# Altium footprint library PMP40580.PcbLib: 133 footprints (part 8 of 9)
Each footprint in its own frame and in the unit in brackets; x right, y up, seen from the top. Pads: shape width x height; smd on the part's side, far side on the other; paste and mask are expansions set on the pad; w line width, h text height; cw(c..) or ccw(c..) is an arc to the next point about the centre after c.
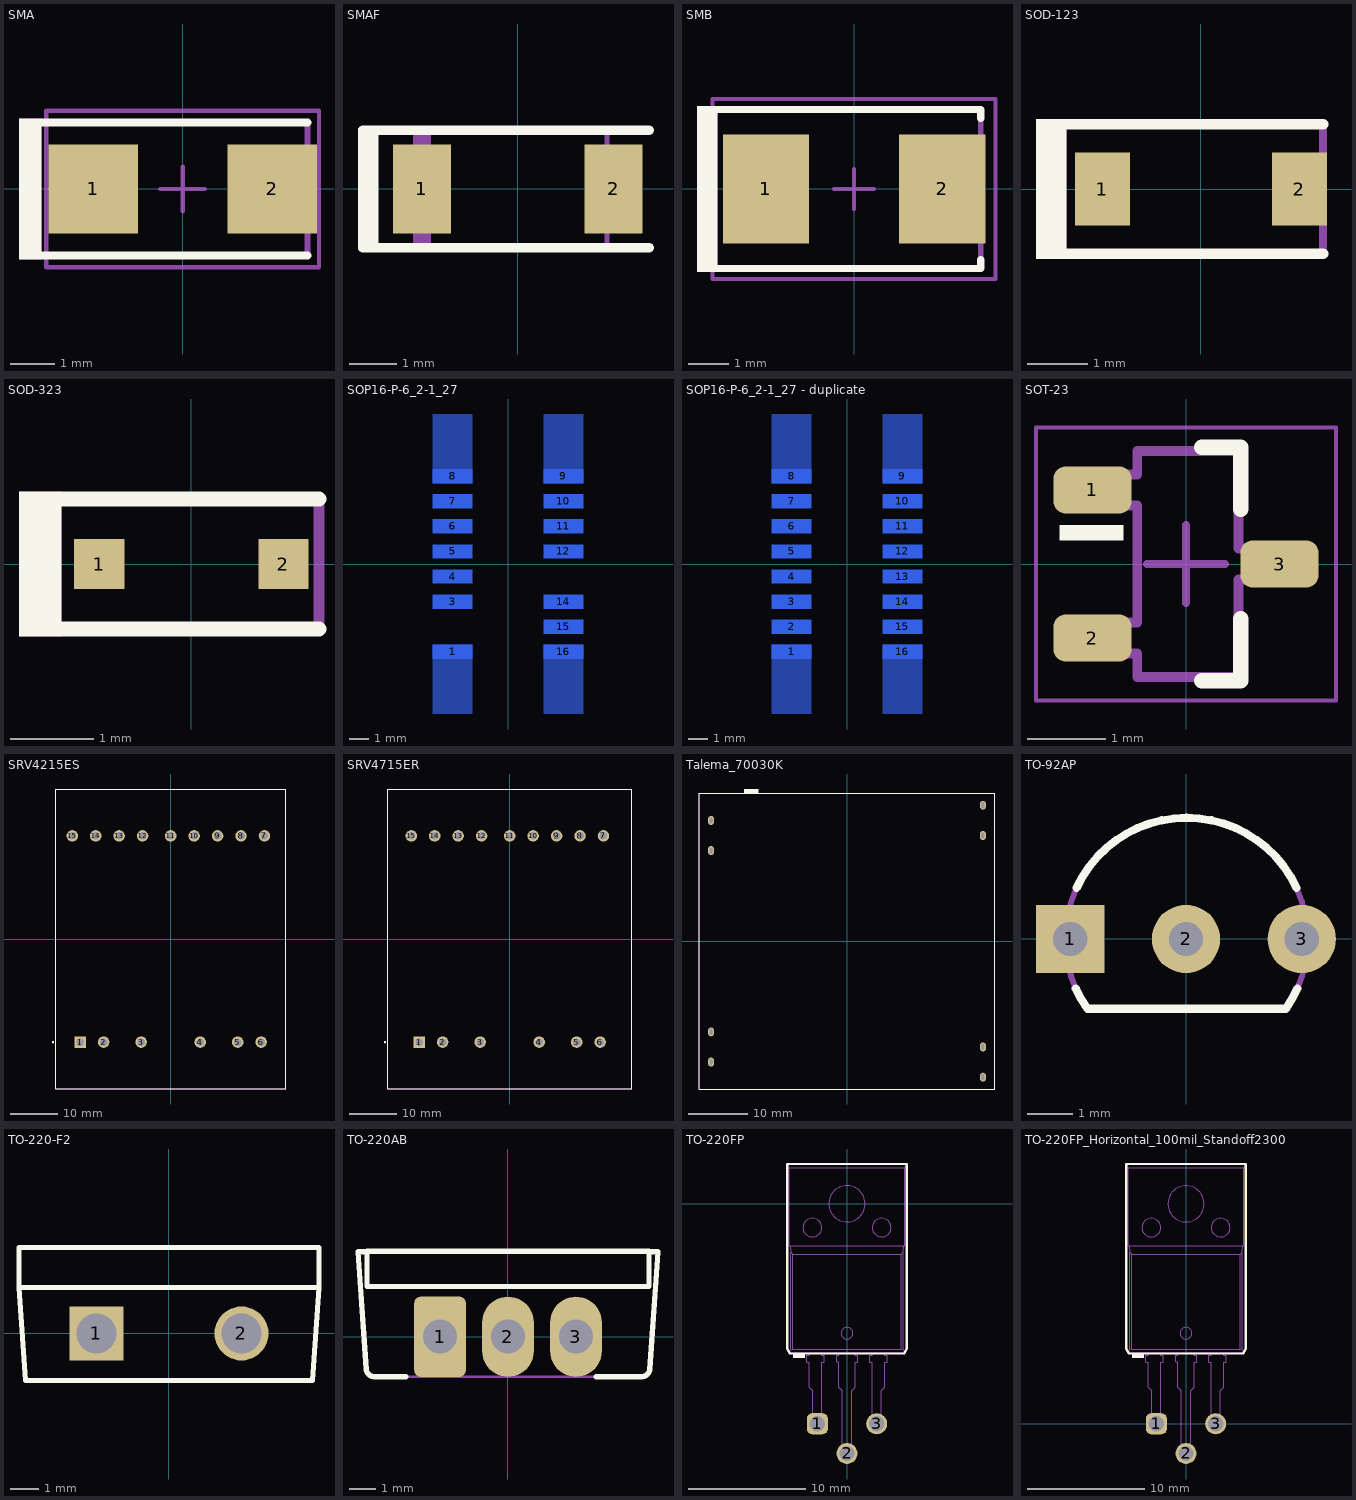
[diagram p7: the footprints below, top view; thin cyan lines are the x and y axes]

## SMA [mm] "Molded Diode, 2-Leads, Body 4.3x2.6mm, IPC Medium Density, based on OnSemi component dimensions and land pattern"
height 2.27
pads (2):
  rect 2x2 smd: 1(-2,0) 2(2,0)
Top Overlay:
  rectangle: -3.658,-1.575 -3.15,1.575
  lines w0.178: -3.327,-1.486 2.794,-1.486 ; -3.327,1.486 2.794,1.486
Mechanical 5:
  rectangle: -3.658,-1.575 -3.15,1.575
  lines w0.127: -3.327,-1.486 2.794,-1.486 2.794,1.486 -3.327,1.486
  text ".Designator" at -2.769,-0.33 h1.02
Mechanical 15:
  lines w0.1: -0.5,0 0.5,0 ; 0,-0.5 0,0.5 ; -3.05,-1.75 -3.05,1.75 3.05,1.75 3.05,-1.75 -3.05,-1.75
3D body "SMA_nominal.stp": height 2.42, standoff 0.02, extent -2.6,-1.3 2.6,1.3

## SMAF [mm] "SMD, 2-Leads, Body 3.8x2.5mm"
height 1
pads (2):
  rect 1.24x1.89 smd: 1(-2.04,0) 2(2.04,0)
Top Overlay:
  rectangle: -3.4,-1.3 -2.96,1.3
  lines w0.2: -3.3,-1.25 2.8,-1.25 ; -3.3,1.25 2.8,1.25
Mechanical 5:
  rectangle: -2.23,-1.3 -1.9,1.3
  lines w0.1: -1.9,-0.875 -1.9,-1.25 1.9,-1.25 1.9,-0.875 ; -1.9,0.875 -1.9,1.25 1.9,1.25 1.9,0.875 ; -1.878,-0.875 -1.878,0.875 ; 1.878,-0.875 1.878,0.875
  text ".Designator" at -1.499,-0.33 h0.9
3D body "SMAF.stp": height 1, standoff 0, extent -2.35,-1.25 2.35,1.25

## SMB [mm] "Molded Diode, 2-Leads, Body 5.4x3.6mm, IPC Medium Density, based on OnSemi component dimensions"
height 2.65
pads (2):
  rect 2.159x2.743 smd: 1(-2.21,0) 2(2.21,0)
Top Overlay:
  rectangle: -3.937,-2.083 -3.429,2.083
  lines w0.178: -3.607,-1.994 3.175,-1.994 3.175,-1.765 ; -3.607,1.994 3.175,1.994 3.175,1.765
Mechanical 5:
  rectangle: -3.937,-2.083 -3.429,2.083
  lines w0.127: -3.607,-1.994 3.175,-1.994 3.175,-1.765 3.175,1.765 3.175,1.994 -3.607,1.994
  text ".Designator" at -2.311,-0.508 h1.02
Mechanical 15:
  lines w0.1: -0.5,0 0.5,0 ; 0,-0.5 0,0.5 ; -3.55,-2.25 -3.55,2.25 3.55,2.25 3.55,-2.25 -3.55,-2.25
3D body "SMB_nominal.stp": height 2.32, standoff 0.02, extent -2.7,-1.8 2.7,1.8

## SOD-123 [mm] "On Semi recommended land pattern"
height 1.35
pads (2):
  rect 0.915x1.22 smd: 1(-1.637,0) 2(1.637,0)
Top Overlay:
  rectangle: -2.743,-1.168 -2.235,1.168
  lines w0.178: -2.413,-1.079 2.032,-1.079 ; -2.413,1.079 2.032,1.079
Mechanical 5:
  rectangle: -2.743,-1.168 -2.235,1.168
  lines w0.127: -2.413,-1.079 2.032,-1.079 2.032,1.079 -2.413,1.079
  text ".Designator" at -1.956,-0.33 h0.76
3D body "SOD-123.stp": height 1.35, standoff 0, extent -1.932,-0.9 1.932,0.9

## SOD-323 [mm] "NXP recommended land pattern"
height 1.15
pads (2):
  rect 0.6x0.6 smd paste-0.05: 1(-1.1,0) 2(1.1,0)
Top Overlay:
  rectangle: -2.057,-0.864 -1.549,0.864
  lines w0.178: -1.803,-0.775 0.1,-0.775 1.525,-0.775 ; -1.803,0.775 0.1,0.775 1.525,0.775
Mechanical 5:
  rectangle: -2.057,-0.864 -1.549,0.864
  lines w0.127: -1.803,-0.775 0.1,-0.775 1.525,-0.775 1.525,0.775 0.1,0.775 -1.803,0.775
  text ".Designator" at -1.4,-0.275 h0.76
3D body "SOD-323.stp": height 1.1, standoff 0, extent -1.3,-0.675 1.3,0.675

## SOP16-P-6_2-1_27 [mm]
pads (14):
  rect 2x0.7 smd far side: 1(-2.8,-4.445) 3(-2.8,-1.905) 4(-2.8,-0.635) 5(-2.8,0.635) 6(-2.8,1.905) 7(-2.8,3.175) 8(-2.8,4.445) 9(2.8,4.445) 10(2.8,3.175) 11(2.8,1.905) 12(2.8,0.635) 14(2.8,-1.905) 15(2.8,-3.175) 16(2.8,-4.445)
Bottom Layer:
  region: -3.8,-7.592 -3.8,-4.092 -1.8,-4.092 -1.8,-7.592
  region: 1.8,-7.592 1.8,-4.092 3.8,-4.092 3.8,-7.592
  region: 1.8,4.093 1.8,7.593 3.8,7.593 3.8,4.093
  region: -3.8,4.093 -3.8,7.593 -1.8,7.593 -1.8,4.093
Bottom Overlay:
  circle w0.5: c-1.05,-5.945 r0.25
  circle w0.15: c-0.9,-4.445 r0.224
  lines w0.15: -1.3,-5.145 -1.3,5.145 1.3,5.145 1.3,-5.145 0.4,-5.145 0.4,-4.502 -0.4,-4.502 -0.4,-5.145 -1.3,-5.145
  lines w0.5: -3.8,-3.81 -1.8,-3.81 ; -3.8,-2.54 -1.8,-2.54 ; -3.8,-1.27 -1.8,-1.27 ; -3.8,0 -1.8,0 ; -3.8,1.27 -1.8,1.27 ; -3.8,2.54 -1.8,2.54 ; -3.8,3.81 -1.8,3.81 ; 1.8,-3.81 3.8,-3.81 ; 1.8,-2.54 3.8,-2.54 ; 1.8,-1.27 3.8,-1.27 ; 1.8,0 3.8,0 ; 1.8,1.27 3.8,1.27 ; 1.8,2.54 3.8,2.54 ; 1.8,3.81 3.8,3.81

## SOP16-P-6_2-1_27 - duplicate [mm]
pads (16):
  rect 2x0.7 smd far side: 1(-2.8,-4.445) 2(-2.8,-3.175) 3(-2.8,-1.905) 4(-2.8,-0.635) 5(-2.8,0.635) 6(-2.8,1.905) 7(-2.8,3.175) 8(-2.8,4.445) 9(2.8,4.445) 10(2.8,3.175) 11(2.8,1.905) 12(2.8,0.635) 13(2.8,-0.635) 14(2.8,-1.905) 15(2.8,-3.175) 16(2.8,-4.445)
Bottom Layer:
  region: -3.8,-7.592 -3.8,-4.092 -1.8,-4.092 -1.8,-7.592
  region: 1.8,-7.592 1.8,-4.092 3.8,-4.092 3.8,-7.592
  region: 1.8,4.093 1.8,7.593 3.8,7.593 3.8,4.093
  region: -3.8,4.093 -3.8,7.593 -1.8,7.593 -1.8,4.093
Bottom Overlay:
  circle w0.5: c-1.05,-5.945 r0.25
  circle w0.15: c-0.9,-4.445 r0.224
  lines w0.15: -1.3,-5.145 -1.3,5.145 1.3,5.145 1.3,-5.145 0.4,-5.145 0.4,-4.502 -0.4,-4.502 -0.4,-5.145 -1.3,-5.145
  lines w0.5: -3.8,-3.81 -1.8,-3.81 ; -3.8,-2.54 -1.8,-2.54 ; -3.8,-1.27 -1.8,-1.27 ; -3.8,0 -1.8,0 ; -3.8,1.27 -1.8,1.27 ; -3.8,2.54 -1.8,2.54 ; -3.8,3.81 -1.8,3.81 ; 1.8,-3.81 3.8,-3.81 ; 1.8,-2.54 3.8,-2.54 ; 1.8,-1.27 3.8,-1.27 ; 1.8,0 3.8,0 ; 1.8,1.27 3.8,1.27 ; 1.8,2.54 3.8,2.54 ; 1.8,3.81 3.8,3.81

## SOT-23 [mm] "SOT23, 3-Leads, Body 2.9x1.3mm, Pitch 0.95mm, Lead Span 2.5mm, IPC Medium Density"
height 1.1
pads (3):
  rrect50% 1x0.6 smd: 1(-1.2,0.95) 2(-1.2,-0.95) 3(1.2,0)
Top Overlay:
  rectangle: -1.625,0.3 -0.8,0.5
  lines w0.2: 0.2,-1.5 0.7,-1.5 0.7,-0.7 ; 0.2,1.5 0.7,1.5 0.7,0.7
Mechanical 5:
  lines w0.127: -1.16,-1.15 -1.16,-0.75 -0.625,-0.75 -0.625,0.75 -1.16,0.75 -1.16,1.15 -0.625,1.15 -0.625,1.45 0.675,1.45 0.675,0.2 1.21,0.2 1.21,-0.2 0.675,-0.2 0.675,-1.45 -0.625,-1.45 -0.625,-1.15 -1.16,-1.15
  text ".Designator" at -0.175,1.225 h0.64
Mechanical 15:
  lines w0.05: -1.925,-1.75 1.925,-1.75 1.925,1.75 -1.925,1.75 -1.925,-1.75
  lines w0.1: -0.5,0 0.5,0 ; 0,-0.5 0,0.5
3D body "SW3dPS-sot-3p290x130ll237h100.STEP": height 1, standoff 0, extent -1.16,-1.45 1.21,1.45

## SRV4215ES [mm]
pads (15):
  rrect4% 2.45x2.45 hole 1.6 paste-1000 mask+0: 1(-19.3,-22)
  round 2.45 hole 1.6 paste-1000 mask+0: 2(-14.3,-22) 3(-6.3,-22) 4(6.3,-22) 5(14.3,-22) 6(19.3,-22) 7(20,22) 8(15,22) 9(10,22) 10(5,22) 11(0,22) 12(-6,22) 13(-11,22) 14(-16,22) 15(-21,22)
Top Overlay:
  circle w0.25: c-25.1,-22 r0.125
  lines w0.2: -24.5,-32 -24.5,32 24.5,32 24.5,-32 -24.5,-32
Mechanical 5:
  lines w0.1: -24.5,-32 -24.5,32 24.5,32 24.5,-32 -24.5,-32
  text ".Designator" at 0,0 h0.5
3D body "Trans_SRV4215ES_SMT_TRANSFORMER.STEP": height 0.25, standoff 0, extent -24.6,-32.1 24.6,32.1

## SRV4715ER [mm]
pads (15):
  rrect4% 2.45x2.45 hole 1.6 paste-1000 mask+0: 1(-19.3,-22)
  round 2.45 hole 1.6 paste-1000 mask+0: 2(-14.3,-22) 3(-6.3,-22) 4(6.3,-22) 5(14.3,-22) 6(19.3,-22) 7(20,22) 8(15,22) 9(10,22) 10(5,22) 11(0,22) 12(-6,22) 13(-11,22) 14(-16,22) 15(-21,22)
Top Overlay:
  circle w0.25: c-26.6,-22 r0.125
  lines w0.2: -26,-32 26,-32 26,32 -26,32 -26,-32
Mechanical 5:
  lines w0.1: -26,-32 26,-32 26,32 -26,32 -26,-32
  text ".Designator" at 0,0 h0.5
3D body "Trans_SRV4715ER_PTH_TRANSFORMER_64MM0_52MM0.STEP": height 0.25, standoff 0, extent -26.1,-32.1 26.1,32.1

## Talema_70030K [mm] "TH, 8-Leads, Body 49.7x49.7mm"
height 23.1
pads (8):
  oval 1x1.5 hole 0.5 slot 1 at 90 deg: 3(-22.86,20.32) 4(-22.86,15.24) 5(-22.86,-15.24) 6(-22.86,-20.32) 11(22.86,-22.86) 12(22.86,-17.78) 13(22.86,17.78) 14(22.86,22.86)
Top Overlay:
  rectangle: -17.3,24.85 -14.9,25.6
  lines w0.2: -24.85,-24.85 -24.85,24.85 24.85,24.85 24.85,-24.85 -24.85,-24.85
Mechanical 5:
  lines w0.1: -24.85,-24.85 24.85,-24.85 24.85,24.85 -24.85,24.85 -24.85,-24.85

## TO-92AP [mm] "TO, Flat Index; 3 In-Line, Axial Leads; Body Dia. 5mm; Leads 0.55 x 0.50 mm (max)"
height 5.2
pads (3):
  rect 1.5x1.5 hole 0.75: 1(-2.54,0)
  round 1.5 hole 0.75: 2(0,0) 3(2.54,0)
Top Overlay:
  lines w0.178: -2.417,-1.082 ccw(c0.013,0) -2.163,-1.53 2.189,-1.53 ccw(c0.013,0) 2.443,-1.082 ; -2.398,1.124 cw(c0.013,0) 2.424,1.124
Mechanical 5:
  lines w0.127: -2.635,-0.25 -2.875,-0.25 -2.875,0.25 -2.635,0.25 ; 2.661,-0.25 2.865,-0.25 2.865,0.25 2.661,0.25 ; -2.647,0 cw(c0.013,0) 2.673,0 cw(c0.013,0) 2.189,-1.53 -2.163,-1.53 cw(c0.013,0) -2.647,0
  text ".Designator" at -1.9,-0.5 h1.02
3D body "TO-92AP.stp": height 9.33, standoff -8.7, extent -2.87,-1.53 2.87,2.66

## TO-220-F2 [mm] "CREE"
height 20.066
pads (2):
  rect 1.9x1.9 hole 1.4: 1(-2.54,0)
  round 1.9 hole 1.4: 2(2.54,0)
Top Overlay:
  lines w0.178: -5.255,1.608 -5.255,3.008 5.255,3.008 5.255,1.608 ; -5.255,1.608 5.255,1.608 ; -5.255,1.608 -5.028,-1.642 5.028,-1.642 5.255,1.608
Mechanical 5:
  lines w0.127: -5.255,1.608 -5.028,-1.642 5.028,-1.642 5.255,1.608 ; -5.255,1.608 5.255,1.608 ; -5.255,1.608 -5.255,3.008 5.255,3.008 5.255,1.608
  text ".Designator" at -4.064,-0.308 h1.02
3D body "TO-220AC.stp": height 19.09, standoff -3.99, extent -5.255,-1.645 5.255,3.008

## TO-220AB [mm] "Copied from Altium's version of TO3B"
height 19.4
pads (3):
  rrect25% 1.93x3 hole 1.27: 1(-2.54,0)
  oval 1.93x3 hole 1.27: 2(0,0) 3(2.54,0)
Top Overlay:
  lines w0.2: -5.27,3.175 -5.606,3.175 ; -5.27,3.185 -5.606,3.185 -5.606,3.175 ; -3.81,-1.495 -5,-1.495 cw(c-5,-1.195) -5.297,-1.237 cw(c-5,-1.195) -5.299,-1.216 -5.606,3.175 ; 3.302,-1.495 5,-1.495 ccw(c5,-1.195) 5.297,-1.237 ccw(c5,-1.195) 5.3,-1.216 5.607,3.175 ; 5.27,3.175 5.607,3.175 ; 5.27,3.185 5.607,3.185 5.607,3.175 ; -5.27,1.875 -5.27,3.195 5.27,3.195 5.27,1.875 -5.27,1.875
Mechanical 5:
  lines w0.1: -5.27,3.175 -5.606,3.175 ; -5.27,3.185 -5.606,3.185 -5.606,3.175 ; 5.27,3.175 5.607,3.175 ; 5.27,3.185 5.607,3.185 5.607,3.175 ; -5.606,3.175 -5.299,-1.216 ccw(c-5,-1.195) -5.297,-1.237 ccw(c-5,-1.195) -5,-1.495 5,-1.495 ccw(c5,-1.195) 5.297,-1.237 ccw(c5,-1.195) 5.3,-1.216 5.607,3.175 ; -5.27,1.875 5.27,1.875 5.27,3.195 -5.27,3.195 -5.27,1.875
  text ".Designator" at -1.524,-0.508 h1.02
3D body "TO-220AB.stp": height 19.42, standoff -3.88, extent -5.606,-1.495 5.607,3.195

## TO-220FP [mm] "TH, 3-Leads, Body 10.4x16mm"
height 6.9
pads (3):
  rrect50% 1.8x1.8 hole 1.3: 1(-2.54,-18.796)
  round 1.8 hole 1.3: 2(0,-21.336) 3(2.54,-18.796)
Top Overlay:
  rectangle: -4.6,-13.196 -3.6,-12.796
  lines w0.2: -5.1,-12.396 -5.1,3.404 5.1,3.404 5.1,-12.396 4.9,-12.796 3.5,-12.796 -4.9,-12.796 -5.1,-12.396
Mechanical 5:
  circle w0.1: c0,0.009 r1.55
  lines w0.1: -5.09,3.391 -5.09,-12.458 -4.917,-12.741 -4.883,-12.741 ; -5.09,3.391 -4.927,3.109 ; -5.09,3.391 -4.95,3.409 4.95,3.409 5.09,3.391 ; -4.927,3.109 -4.927,-3.591 -4.847,-3.591 ; -4.927,3.109 4.927,3.109 ; -4.883,-12.741 -4.81,-12.477 ; -4.883,-12.741 4.883,-12.741 ; -4.847,-3.591 4.847,-3.591 ; -4.847,-3.591 -4.81,-4.149 ; -4.81,-12.477 -4.65,-12.441 ; -4.81,-12.477 -4.81,-4.149 ; -4.81,-4.149 -4.65,-4.298 ; -4.65,-12.441 -4.65,-4.298 ; -4.65,-12.441 4.65,-12.441 ; -4.65,-4.298 4.65,-4.298 ; -2.94,-18.041 -2.14,-18.041 ; -2.94,-18.041 -2.94,-15.991 -3.24,-15.691 -3.24,-13.541 -3.44,-13.541 -3.44,-12.941 -3.24,-12.941 -3.24,-12.741 -2.14,-12.741 -2.14,-12.941 -1.94,-12.941 -1.94,-13.541 -2.14,-13.541 -2.14,-18.041 ; -2.94,-18.041 -2.94,-19.041 -2.14,-19.041 -2.14,-18.041 ; -0.4,-20.581 0.4,-20.581 ; -0.4,-20.581 -0.4,-15.991 -0.7,-15.691 -0.7,-13.509 -0.897,-13.509 -0.897,-12.941 -0.7,-12.941 -0.7,-12.741 0.7,-12.741 0.7,-12.941 0.9,-12.941 0.9,-13.541 0.7,-13.541 0.7,-15.691 0.4,-15.991 0.4,-20.581 ; -0.4,-20.581 -0.4,-21.581 0.4,-21.581 0.4,-20.581 ; 2.14,-18.041 2.94,-18.041 ; 2.14,-18.041 2.14,-13.541 1.94,-13.541 1.94,-12.941 2.14,-12.941 2.14,-12.741 3.24,-12.741 3.24,-12.941 3.44,-12.941 3.44,-13.541 3.24,-13.541 3.24,-15.691 2.94,-15.991 2.94,-18.041 ; 2.14,-18.041 2.14,-19.041 2.94,-19.041 2.94,-18.041 ; 4.65,-12.441 4.65,-4.298 ; 4.65,-12.441 4.81,-12.477 ; 4.65,-4.298 4.81,-4.149 ; 4.81,-12.477 4.81,-4.149 ; 4.81,-12.477 4.883,-12.741 ; 4.81,-4.149 4.847,-3.591 ; 4.847,-3.591 4.927,-3.591 4.927,3.109 ; 4.883,-12.741 4.917,-12.741 5.09,-12.458 5.09,3.391 ; 4.927,3.109 5.09,3.391 ; -3.768,-2.029 ccw(c-2.968,-2.029) -2.168,-2.029 ccw(c-2.968,-2.029) -3.768,-2.029 ; -0.5,-11.055 cw(c0,-11.055) 0.5,-11.055 cw(c0,-11.055) -0.5,-11.055 ; 2.168,-2.029 ccw(c2.968,-2.029) 3.768,-2.029 ccw(c2.968,-2.029) 2.168,-2.029
  text ".Designator" at -3.1,-9.996 h1.85
3D body "TO-220FP_Horizontal_100mil_Standoff2300.stp": height 7.02, standoff -1.57, extent -5.09,-21.581 5.09,3.409

## TO-220FP_Horizontal_100mil_Standoff2300 [mm] "TH, 3-Leads, Body 10.4x16mm"
height 6.9
pads (3):
  rrect50% 1.8x1.8 hole 1.3: 1(-2.54,0)
  round 1.8 hole 1.3: 2(0,-2.54) 3(2.54,0)
Top Overlay:
  rectangle: -4.6,5.6 -3.6,6
  lines w0.2: -5.1,6.4 -5.1,22.2 5.1,22.2 5.1,6.4 4.9,6 3.5,6 -4.9,6 -5.1,6.4
Mechanical 5:
  lines w0.1: -5.09,22.187 -5.09,6.338 -4.917,6.055 -4.883,6.055 ; -5.09,22.187 -4.927,21.905 ; -5.09,22.187 -4.95,22.205 4.95,22.205 5.09,22.187 ; -4.927,21.905 -4.927,15.205 -4.847,15.205 ; -4.927,21.905 4.927,21.905 ; -4.883,6.055 -4.81,6.319 ; -4.883,6.055 4.883,6.055 ; -4.847,15.205 4.847,15.205 ; -4.847,15.205 -4.81,14.647 ; -4.81,6.319 -4.65,6.355 ; -4.81,6.319 -4.81,14.647 ; -4.81,14.647 -4.65,14.498 ; -4.65,6.355 -4.65,14.498 ; -4.65,6.355 4.65,6.355 ; -4.65,14.498 4.65,14.498 ; -2.94,0.755 -2.14,0.755 ; -2.94,0.755 -2.94,2.805 -3.24,3.105 -3.24,5.255 -3.44,5.255 -3.44,5.855 -3.24,5.855 -3.24,6.055 -2.14,6.055 -2.14,5.855 -1.94,5.855 -1.94,5.255 -2.14,5.255 -2.14,0.755 ; -2.94,0.755 -2.94,-0.245 -2.14,-0.245 -2.14,0.755 ; -0.4,-1.785 0.4,-1.785 ; -0.4,-1.785 -0.4,2.805 -0.7,3.105 -0.7,5.287 -0.897,5.287 -0.897,5.855 -0.7,5.855 -0.7,6.055 0.7,6.055 0.7,5.855 0.9,5.855 0.9,5.255 0.7,5.255 0.7,3.105 0.4,2.805 0.4,-1.785 ; -0.4,-1.785 -0.4,-2.785 0.4,-2.785 0.4,-1.785 ; 2.14,0.755 2.94,0.755 ; 2.14,0.755 2.14,5.255 1.94,5.255 1.94,5.855 2.14,5.855 2.14,6.055 3.24,6.055 3.24,5.855 3.44,5.855 3.44,5.255 3.24,5.255 3.24,3.105 2.94,2.805 2.94,0.755 ; 2.14,0.755 2.14,-0.245 2.94,-0.245 2.94,0.755 ; 4.65,6.355 4.65,14.498 ; 4.65,6.355 4.81,6.319 ; 4.65,14.498 4.81,14.647 ; 4.81,6.319 4.81,14.647 ; 4.81,6.319 4.883,6.055 ; 4.81,14.647 4.847,15.205 ; 4.847,15.205 4.927,15.205 4.927,21.905 ; 4.883,6.055 4.917,6.055 5.09,6.338 5.09,22.187 ; 4.927,21.905 5.09,22.187 ; -3.768,16.767 ccw(c-2.968,16.767) -2.168,16.767 ccw(c-2.968,16.767) -3.768,16.767 ; -1.55,18.805 ccw(c0,18.805) 1.55,18.805 ccw(c0,18.805) -1.55,18.805 ; -0.5,7.741 cw(c0,7.741) 0.5,7.741 cw(c0,7.741) -0.5,7.741 ; 2.168,16.767 ccw(c2.968,16.767) 3.768,16.767 ccw(c2.968,16.767) 2.168,16.767
  text ".Designator" at -3.1,8.8 h1.85
3D body "TO-220FP_Horizontal_100mil_Standoff2300.stp": height 7.02, standoff -1.57, extent -5.09,-2.785 5.09,22.205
